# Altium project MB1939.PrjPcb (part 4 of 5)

## Sheet Power.SchDoc: Schematic sheet title to update
size A3; Date: Not used; ApprovedBy: Not used; CheckedBy: Not used; Author: Not used; CompanyName: STMicroelectronics; DrawnBy: Not used; Engineer: Not used; Organization: Not used; Address1: Not used; Address2: Not used; Address3: Not used; Address4: Not used; DocumentNumber: Not used; Revision: Not used; SheetNumber: 5; SheetTotal: 21
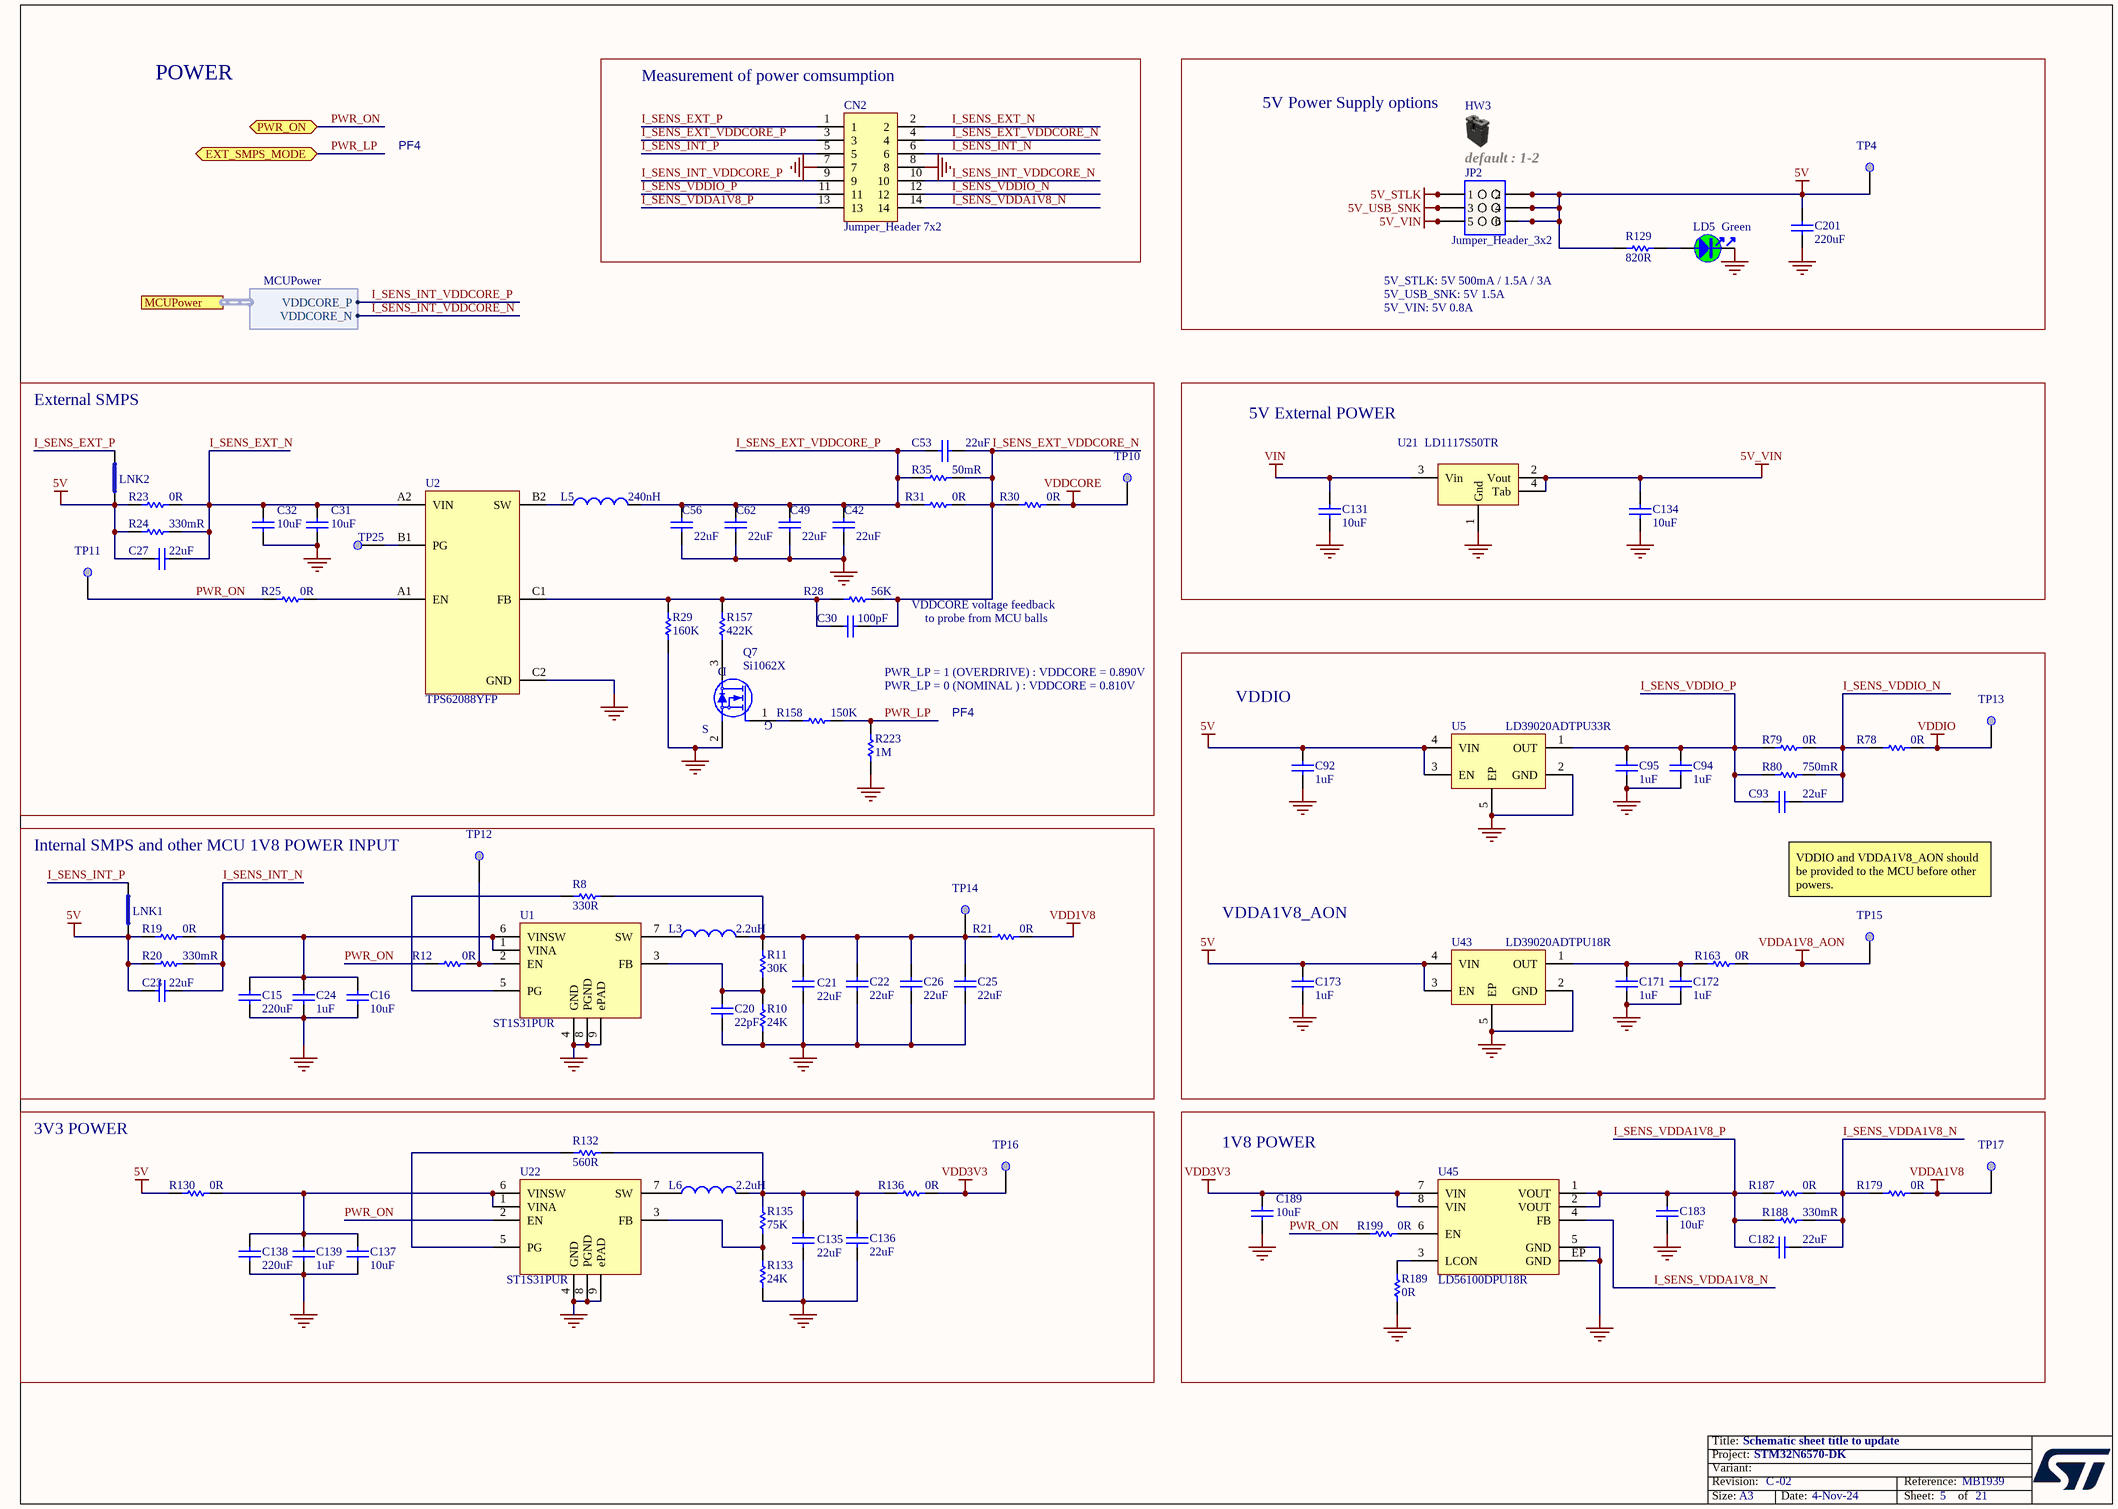
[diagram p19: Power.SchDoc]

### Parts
C15  value 220uF  [C1206_H1P6]  (hidden comment: Capacitor)
C16  value 10uF  [C0603]  (hidden comment: Capacitor)
C20  value 22pF  [C0402]  (hidden comment: Capacitor)
C21  value 22uF  [C0603]  (hidden comment: Capacitor)
C22  value 22uF  [C0603]  (hidden comment: Capacitor)
C23  value 22uF  [C0603]  (hidden comment: Capacitor)
C24  value 1uF  [C0402]  (hidden comment: Capacitor)
C25  value 22uF  [C0603]  (hidden comment: Capacitor)
C26  value 22uF  [C0603]  (hidden comment: Capacitor)
C27  value 22uF  [C0603]  (hidden comment: Capacitor)
C30  value 100pF  [C0402]  (hidden comment: Capacitor)
C31  value 10uF  [C0603]  (hidden comment: Capacitor)
C32  value 10uF  [C0603]  (hidden comment: Capacitor)
C42  value 22uF  [C0603]  (hidden comment: Capacitor)
C49  value 22uF  [C0603]  (hidden comment: Capacitor)
C53  value 22uF  [C0603]  (hidden comment: Capacitor)
C56  value 22uF  [C0603]  (hidden comment: Capacitor)
C62  value 22uF  [C0603]  (hidden comment: Capacitor)
C92  value 1uF  [C0402]  (hidden comment: Capacitor)
C93  value 22uF  [C0603]  (hidden comment: Capacitor)
C94  value 1uF  [C0402]  (hidden comment: Capacitor)
C95  value 1uF  [C0402]  (hidden comment: Capacitor)
C131  value 10uF  [C0805]  (hidden comment: Capacitor)
C134  value 10uF  [C0805]  (hidden comment: Capacitor)
C135  value 22uF  [C0603]  (hidden comment: Capacitor)
C136  value 22uF  [C0603]  (hidden comment: Capacitor)
C137  value 10uF  [C0603]  (hidden comment: Capacitor)
C138  value 220uF  [C1206_H1P6]  (hidden comment: Capacitor)
C139  value 1uF  [C0402]  (hidden comment: Capacitor)
C171  value 1uF  [C0402]  (hidden comment: Capacitor)
C172  value 1uF  [C0402]  (hidden comment: Capacitor)
C173  value 1uF  [C0402]  (hidden comment: Capacitor)
C182  value 22uF  [C0603]  (hidden comment: Capacitor)
C183  value 10uF  [C0603]  (hidden comment: Capacitor)
C189  value 10uF  [C0603]  (hidden comment: Capacitor)
C201  value 220uF  [C1206_H1P6]  (hidden comment: Capacitor)
CN2  value Jumper_Header 7x2  [CON_SAMTEC_TSW-107-07-X-D]  (hidden comment: Header 7x2)
HW3  Shunt Black 2.54mm  (value not drawn)  (mechanical)
JP2  value Jumper_Header_3x2  [CON_SAMTEC_TSM-103-01-X-DV]  (hidden comment: Jumper_Header 3x2)
L3  value 2.2uH  [IND_4025_WURTH_74404043022A]  (hidden comment: Inductor)
L5  value 240nH  [IND_MURATA_DFE201612P]  (hidden comment: Inductor)
L6  value 2.2uH  [IND_4025_WURTH_74404043022A]  (hidden comment: Inductor)
LD5  value Green  [LED_0603_OSRAM_LG-Q396-PS-35_GREEN_1A2K_H0P4]  (hidden comment: LED_green)
LNK1  link_200  [LINK200]  (value not drawn)  (no BOM)
LNK2  link_200  [LINK200]  (value not drawn)  (no BOM)
Q7  Manufacturer_Part_Number: Si1062X  [MOS_SC89-3L]  (hidden comment: MOSFET_N-CHANNEL)
R8  value 330R  [R0402]  (hidden comment: Resistor)
R10  value 24K  [R0402]  (hidden comment: Resistor)
R11  value 30K  [R0402]  (hidden comment: Resistor)
R12  value 0R  [R0402]  (hidden comment: Resistor)
R19  value 0R  [R0603]  (hidden comment: Resistor)
R20  value 330mR  [R0603]  (hidden comment: Resistor)
R21  value 0R  [R0603]  (hidden comment: Resistor)
R23  value 0R  [R0603]  (hidden comment: Resistor)
R24  value 330mR  [R0603]  (hidden comment: Resistor)
R25  value 0R  [R0402]  (hidden comment: Resistor)
R28  value 56K  [R0402]  (hidden comment: Resistor)
R29  value 160K  [R0402]  (hidden comment: Resistor)
R30  value 0R  [R0603]  (hidden comment: Resistor)
R31  value 0R  [R0603]  (hidden comment: Resistor)
R35  value 50mR  [R0603]  (hidden comment: Resistor)
R78  value 0R  [R0603]  (hidden comment: Resistor)
R79  value 0R  [R0603]  (hidden comment: Resistor)
R80  value 750mR  [R0603]  (hidden comment: Resistor)
R129  value 820R  [R0603]  (hidden comment: Resistor)
R130  value 0R  [R0603]  (hidden comment: Resistor)
R132  value 560R  [R0402]  (hidden comment: Resistor)
R133  value 24K  [R0402]  (hidden comment: Resistor)
R135  value 75K  [R0402]  (hidden comment: Resistor)
R136  value 0R  [R0603]  (hidden comment: Resistor)
R157  value 422K  [R0402]  (hidden comment: Resistor)
R158  value 150K  [R0402]  (hidden comment: Resistor)
R163  value 0R  [R0805]  (hidden comment: Resistor)
R179  value 0R  [R0603]  (hidden comment: Resistor)
R187  value 0R  [R0603]  (hidden comment: Resistor)
R188  value 330mR  [R0603]  (hidden comment: Resistor)
R189  value 0R  [R0402]  (hidden comment: Resistor)
R199  value 0R  [R0603]  (hidden comment: Resistor)
R223  value 1M  [R0402]  (hidden comment: Resistor)
TP4  Test Point  [TP_SMD_2MM]  (value not drawn)  (no BOM)
TP10  Test Point  [TP_SMD_2MM]  (value not drawn)  (no BOM)
TP11  Test Point  [TP_SMD_2MM]  (value not drawn)  (no BOM)
TP12  Test Point  [TP_SMD_2MM]  (value not drawn)  (no BOM)
TP13  Test Point  [TP_SMD_2MM]  (value not drawn)  (no BOM)
TP14  Test Point  [TP_SMD_2MM]  (value not drawn)  (no BOM)
TP15  Test Point  [TP_SMD_2MM]  (value not drawn)  (no BOM)
TP16  Test Point  [TP_SMD_2MM]  (value not drawn)  (no BOM)
TP17  Test Point  [TP_SMD_2MM]  (value not drawn)  (no BOM)
TP25  Test Point  [TP_SMD_1MM]  (value not drawn)  (no BOM)
U1  ST1S31PUR  [ICC_VFDFPN8-EPAD_3X3_P065]
U2  TPS62088YFP  [ICC_DSBGA6_YFP_0P80X1P20_H0P50_P040]
U5  value LD39020ADTPU33R  [REG_XDFN4-EPAD_CASE-711AJ_1X1_H0P4_P065]  (hidden comment: LD39020)
U21  LD1117S50TR  [REG_SOT223-TAB]
U22  ST1S31PUR  [ICC_VFDFPN8-EPAD_3X3_P065]
U43  value LD39020ADTPU18R  [REG_XDFN4-EPAD_CASE-711AJ_1X1_H0P4_P065]  (hidden comment: LD39020)
U45  LD56100DPU18R  [ICC_DFN8-EPAD_1P6X1P2_P040_H0P45]

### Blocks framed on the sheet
Measurement of power comsumption: CN2
5V Power Supply options: C201 HW3 JP2 LD5 R129 TP4
External SMPS: C27 C30-C32 C42 C49 C53 C56 C62 L5 LNK2 Q7 R23-R25 R28-R31 R35 R157 R158 R223 TP10 TP11 TP25 U2
5V External POWER: C131 C134 U21
Internal SMPS and other MCU 1V8 POWER INPUT: C15 C16 C20-C26 L3 LNK1 R8 R10-R12 R19-R21 TP12 TP14 U1
3V3 POWER: C135-C139 L6 R130 R132 R133 R135 R136 TP16 U22
1V8 POWER: C182 C183 C189 R179 R187-R189 R199 TP17 U45

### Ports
EXT_SMPS_MODE (bidir), MCUPower (harness MCUPower), PWR_ON (bidir)

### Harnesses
MCUPower: VDDCORE_P, VDDCORE_N

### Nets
5V: C23.2 C27.2 C92.2 C173.2 C201.2 JP2.2 JP2.4 JP2.6 LNK1.2 LNK2.2 R19.1 R20.1 R23.1 R24.1 R129.1 R130.1 TP4.1 U5.3(EN) U5.4(VIN) U43.3(EN) U43.4(VIN)
5V_STLK: JP2.1
5V_USB_SNK: JP2.3
5V_VIN: C134.2 JP2.5 U21.2(Vout) U21.4(Tab)
GND: C15.1 C16.1 C20.1 C21.1 C22.1 C24.1 C25.1 C26.1 C31.1 C32.1 C42.1 C49.1 C56.1 C62.1 C92.1 C94.1 C95.1 C131.1 C134.1 C135.1 C136.1 C137.1 C138.1 C139.1 C171.1 C172.1 C173.1 C183.1 C189.1 C201.1 CN2.7 CN2.8 LD5.2 Q7.2(S) R10.1 R29.1 R133.1 R189.1 R223.1 U1.4(GND) U1.8(PGND) U1.9(ePAD) U2.C2(GND) U5.2(GND) U5.5(EP) U21.1(Gnd) U22.4(GND) U22.8(PGND) U22.9(ePAD) U43.2(GND) U43.5(EP) U45.5(GND) U45.EP(GND)
VDD1V8: R21.2
VDD3V3: C189.2 R136.2 TP16.1 U45.7(VIN) U45.8(VIN)
VDDA1V8: R179.2 TP17.1
VDDA1V8_AON: R163.2 TP15.1
VDDCORE: R30.2 TP10.1
VDDIO: R78.2 TP13.1
VIN: C131.2 U21.3(Vin)
I_SENS_EXT_N: C27.1 C31.2 C32.2 CN2.2 R23.2 R24.2 U2.A2(VIN)
I_SENS_EXT_P: CN2.1 LNK2.1
I_SENS_EXT_VDDCORE_N: C30.2 C53.1 CN2.4 R28.2 R30.1 R31.2 R35.2
I_SENS_EXT_VDDCORE_P: C42.2 C49.2 C53.2 C56.2 C62.2 CN2.3 L5.2 R31.1 R35.1
I_SENS_INT_N: C15.2 C16.2 C23.1 C24.2 CN2.6 R19.2 R20.2 U1.1(VINA) U1.6(VINSW)
I_SENS_INT_P: CN2.5 LNK1.1
I_SENS_INT_VDDCORE_N: CN2.10 ; port MCUPower.VDDCORE_N
I_SENS_INT_VDDCORE_P: CN2.9 ; port MCUPower.VDDCORE_P
I_SENS_VDDA1V8_N: C182.1 CN2.14 R179.1 R187.2 R188.2 U45.4(FB)
I_SENS_VDDA1V8_P: C182.2 C183.2 CN2.13 R187.1 R188.1 U45.1(VOUT) U45.2(VOUT)
I_SENS_VDDIO_N: C93.1 CN2.12 R78.1 R79.2 R80.2
I_SENS_VDDIO_P: C93.2 C94.2 C95.2 CN2.11 R79.1 R80.1 U5.1(OUT)
PWR_LP: R158.1 R223.2 ; port EXT_SMPS_MODE  [project net PF4]
PWR_ON: R12.1 R25.1 R199.1 TP11.1 U22.2(EN) ; port PWR_ON
NetC20_2: C20.2 R10.2 R11.1 U1.3(FB)
NetC21_2: C21.2 C22.2 C25.2 C26.2 L3.2 R8.2 R11.2 R21.1 TP14.1
NetC30_1: C30.1 R28.1 R29.2 R157.2 U2.C1(FB)
NetC135_2: C135.2 C136.2 L6.2 R132.2 R135.2 R136.1
NetC137_2: C137.2 C138.2 C139.2 R130.2 U22.1(VINA) U22.6(VINSW)
NetC171_2: C171.2 C172.2 R163.1 U43.1(OUT)
NetL3_1: L3.1 U1.7(SW)
NetL5_1: L5.1 U2.B2(SW)
NetL6_1: L6.1 U22.7(SW)
NetLD5_1: LD5.1 R129.2
NetQ7_1: Q7.1(G) R158.2
NetQ7_3: Q7.3(D) R157.1
NetR8_1: R8.1 U1.5(PG)
NetR12_2: R12.2 TP12.1 U1.2(EN)
NetR25_2: R25.2 U2.A1(EN)
NetR132_1: R132.1 U22.5(PG)
NetR133_2: R133.2 R135.1 U22.3(FB)
NetR189_2: R189.2 U45.3(LCON)
NetR199_2: R199.2 U45.6(EN)
NetTP25_1: TP25.1 U2.B1(PG)

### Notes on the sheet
- POWER
- PF4
- default : 1-2
- 5V_STLK: 5V 500mA / 1.5A / 3A
- 5V_USB_SNK: 5V 1.5A
- 5V_VIN: 5V 0.8A
- VDDCORE voltage feedback
- to probe from MCU balls
- PWR_LP = 1 (OVERDRIVE) : VDDCORE = 0.890V
- PWR_LP = 0 (NOMINAL ) : VDDCORE = 0.810V
- VDDIO
- VDDA1V8_AON
- VDDIO and VDDA1V8_AON should be provided to the MCU before other powers.

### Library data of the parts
C15 C138 C201 = MCD-00104: Capacitor, MLCC, 220uF, 6V3, X5R, +/-20%, 1206, T=1.6mm; Part_Preference: Recommended; Manufacturer: MURATA; Manufacturer_Part_Number: GRM31CR60J227ME11; Order_Code_RS: 170-6396; Component_Country_Of_Origin: Japan°°; ShowFields: YES; ID: 2764
C16 C137 C183 = MCD-00099: Capacitor, MLCC, 10uF, 10V, X5R, +/-10%, 0603, T=0.8mm; Part_Preference: Recommended; Manufacturer: MURATA; Manufacturer_Part_Number: GRM188R61A106KE69D; Partial_Alternate_Internal_Part_Number: MCD-03152; Order_Code_RS: 2494233; Component_Country_Of_Origin: Japan°°; ShowFields: YES; ID: 2770
C20 = MCD-01783: Capacitor, MLCC, 22pF, 50V, NPO,+/-2%, 0402, T=0.5mm; Part_Preference: Recommended; Manufacturer: YAGEO; Manufacturer_Part_Number: CC0402GRNPO9BN220; Component_Country_Of_Origin: China; ShowFields: YES; ID: 3883
C21 C22 C25 C26 C135 C136 = MCD-00100: Capacitor, MLCC, 22uF, 6V3, X5R, +/-20%, 0603, T=0.8mm; Part_Preference: Recommended; Manufacturer: MURATA; Manufacturer_Part_Number: GRM188R60J226MEA0J; Component_Country_Of_Origin: Japan°°; ShowFields: YES; ID: 2766
C23 C27 C42 C49 C53 C56 C62 C93 C182 = MCD-00100: Capacitor, MLCC, 22uF, 6V3, X5R, +/-20%, 0603, T=0.8mm; Manufacturer_Part_Number: GRM188R60J226MEA0J; Manufacturer: MURATA; Part_Preference: Recommended; Component_Country_Of_Origin: Japan°°; ShowFields: YES; ID: 2766
C24 C92 C94 C95 C139 C171-C173 = MCD-00095: Capacitor, MLCC, 1uF, 25V, X5R, +/-10%, 0402, T=0.5mm; Part_Preference: Recommended; Manufacturer: MURATA; Manufacturer_Part_Number: GRM155R61E105KA12; Partial_Alternate_Internal_Part_Number: MCD-04188; Order_Code_RS: 2218855; Component_Country_Of_Origin: Japan°°; ShowFields: YES; ID: 2772
C30 = MCD-00205: Capacitor, MLCC, 100pF, 50V, NPO, +/-5%, 0402, T=0.5mm; Part_Preference: Recommended; Manufacturer: YAGEO; Manufacturer_Part_Number: CC0402JRNPO9BN101; Component_Country_Of_Origin: China; ShowFields: YES; ID: 2658
C31 C32 = MCD-00099: Capacitor, MLCC, 10uF, 10V, X5R, +/-10%, 0603, T=0.8mm; Manufacturer_Part_Number: GRM188R61A106KE69D; Manufacturer: MURATA; Part_Preference: Recommended; Partial_Alternate_Internal_Part_Number: MCD-03152; Order_Code_RS: 2494233; Component_Country_Of_Origin: Japan°°; ShowFields: YES; ID: 2770
C131 C134 = MCD-00014: Capacitor, MLCC, 10uF, 25V, X5R, +/-10%, 0805, T=0.85mm; Manufacturer_Part_Number: CC0805KRX5R8BB106; Manufacturer: YAGEO; Part_Preference: Recommended; Full_Alternate_Internal_Part_Number: MCD-02385; Partial_Alternate_Internal_Part_Number: MCD-03053; Component_Country_Of_Origin: China; ShowFields: YES; ID: 2468
C189 = MCD-00099: Capacitor, MLCC, 10uF, 10V, X5R, +/-10%, 0603, T=0.8mm; Manufacturer_Part_Number: GRM188R61A106KE69D; Manufacturer: MURATA; Part_Preference: Recommended; Partial_Alternate_Internal_Part_Number: MCD-03152; Order_Code_RS: 2494233; Component_Country_Of_Origin: Japan°°; ID: 2770; ShowFields: YES
CN2 = MCD-02123: Header, 7x2, 2.54mm, VR, TH, T=5.84mm/2.54mm; Part_Preference: Recommended; Part_Type: Connector; Manufacturer: SAMTEC; Manufacturer_Part_Number: TSW-107-07-G-D; Component_Country_Of_Origin: China, Costa Rica, Malaysia, USA, Vietnam; ShowFields: YES; ID: 4223
HW3 = MCD-00043: Jumper, 2.54mm, Black, 4.3A, 6.1mm, 5mR; Part_Type: Misc; Manufacturer: SAMTEC; Part_Preference: Recommended; Full_Alternate_Internal_Part_Number: MCD-02388; Manufacturer_HQ_COO: Unknown; Partial_Alternate_Internal_Part_Number: MCD-01849, MCD-01864; Value: SNT-100-BK-G; Component_Country_Of_Origin: China, Costa Rica, Malaysia, USA, Vietnam; ShowFields: YES; ID: 2551; Order_Code_RS: 158-7784; Alternate_EMS: A
JP2 = MCD-03177: Header, 3x2, 2.54mm, VR, SMD, T=9,65mm; Part_Type: Connector; Part_Preference: Recommended; Manufacturer: SAMTEC; Manufacturer_Part_Number: TSM-103-01-G-DV; ShowFields: YES; ID: 5293; Component_Country_Of_Origin: USA
L3 L6 = MCD-02242: Inductor, 2.2uH, +/-30%, 3,83A, 0R023, 4x4mm, T=2.5mm; Part_Preference: Recommended; Manufacturer: WURTH ELEKTRONIK; Manufacturer_Part_Number: 74404043022A; Component_Country_Of_Origin: Unknown; ShowFields: YES; ID: 4342
L5 = MCD-02477: Inductor, 240nH, +/-20%, 4.4A, 23mR, 0806, T=1.2mm; Part_Preference: Recommended; Manufacturer: MURATA; Manufacturer_Part_Number: DFE201612P-R24M=P2; Order_Code_RS: 167-0599; ShowFields: YES; ID: 4583; Component_Country_Of_Origin: China°
LD5 = MCD-00588: LED, Green, 2V, 20mA, 0603; Part_Preference: Recommended; Part_Type: Display; Manufacturer: OSRAM OPTO SEMICONDUCTORS; Manufacturer_Part_Number: LG Q396-PS-35; Partial_Alternate_Internal_Part_Number: MCD-02400, MCD-03155, MCD-02901; Component_Country_Of_Origin: Unknown; ShowFields: YES; ID: 3155
LNK1 LNK2 = MCD-02777: Track link on PCB 200um width for layout routing; Part_Type: Misc; Part_Preference: Recommended; ShowFields: YES; ID: 4889; Component_Country_Of_Origin: Unknown
Q7 = MCD-02221: Transistor, MOSFET, N-CH, 20V, 530mA, SC89-3; Part_Preference: Recommended; Manufacturer: VISHAY; Order_Code_RS: 812-3044; Component_Country_Of_Origin: Philippines; Value: Si1062X; ShowFields: YES; ID: 4321
R8 = MCD-00062: Resistor, 330R, 0402, +/-1%, 1/16W; Part_Preference: Recommended; Manufacturer: YAGEO; Manufacturer_Part_Number: RC0402FR-07330RL; Order_Code_RS: 9239170; Component_Country_Of_Origin: China; ShowFields: YES; ID: 2529
R10 R133 = MCD-00435: Resistor, 24K, 0402, +/-1%, 1/16W; Part_Preference: Recommended; Manufacturer: YAGEO; Manufacturer_Part_Number: RC0402FR-0724KL; Component_Country_Of_Origin: China; ShowFields: YES; ID: 2845
R11 = MCD-02979: Resistor, 30K, 0402, +/-0.1%, 1/16W, +/-25ppm/°C; Part_Preference: Recommended; Manufacturer: YAGEO; Manufacturer_Part_Number: RT0402BRD0730KL; Order_Code_RS: 199-1325; ShowFields: YES; ID: 5095; Component_Country_Of_Origin: Taiwan
R12 R25 = MCD-00052: Resistor, 0R, 0402, +/-5%, 1/16W; Manufacturer_Part_Number: RC0402JR-070RL; Manufacturer: YAGEO; Part_Preference: Recommended; Order_Code_RS: 9232516RL; Component_Country_Of_Origin: China; ShowFields: YES; ID: 2540
R19 R23 R130 = MCD-00056: Resistor, 0R, 0603, +/-5%, 1/10W; Manufacturer_Part_Number: RC0603JR-070RL; Manufacturer: YAGEO; Part_Preference: Recommended; Order_Code_RS: 9233130RL; Component_Country_Of_Origin: China; ShowFields: YES; ID: 2536
R20 R24 R188 = MCD-03197: Resistor, 330mR, 0603, +/-1%, 1/5W; Part_Preference: Recommended; Manufacturer: YAGEO; Manufacturer_Part_Number: PT0603FR-7W0R33L; Full_Alternate_Internal_Part_Number: MCD-04231; ShowFields: YES; ID: 5313; Component_Country_Of_Origin: Taiwan
R21 R30 R31 R136 = MCD-00181: Resistor, 0R, 0603, +/- 0.5mR, 1/4W; Manufacturer_Part_Number: PMR03EZPJ000; Manufacturer: ROHM SEMICONDUCTOR; Part_Preference: Recommended; Component_Country_Of_Origin: Philippines, Thailand°°; ShowFields: YES; ID: 2691
R28 = MCD-00493: Resistor, 56K, 0402, +/-1%, 1/16W; Part_Preference: Recommended; Manufacturer: YAGEO; Manufacturer_Part_Number: RC0402FR-0756KL; Component_Country_Of_Origin: China; ShowFields: YES; ID: 2784
R29 = MCD-00405: Resistor, 160K, 0402, +/-1%, 1/16W; Part_Preference: Recommended; Manufacturer: YAGEO; Manufacturer_Part_Number: RC0402FR-07160KL; Component_Country_Of_Origin: China; ShowFields: YES; ID: 2873
R35 = MCD-02233: Resistor, 50mR, 0603, +/-1%, 1/3W; Part_Preference: Recommended; Manufacturer: PANASONIC; Manufacturer_Part_Number: ERJ-3BWFR050V; Order_Code_RS: RA; Component_Country_Of_Origin: Japan; ShowFields: YES; ID: 4333
R78 R79 R179 R187 = MCD-00181: Resistor, 0R, 0603, +/- 0.5mR, 1/4W; Part_Preference: Recommended; Manufacturer: ROHM SEMICONDUCTOR; Manufacturer_Part_Number: PMR03EZPJ000; Component_Country_Of_Origin: Philippines, Thailand°°; ShowFields: YES; ID: 2691
R80 = MCD-03198: Resistor, 750mR, 0603, +/-1%, 1/5W; Part_Preference: Recommended; Manufacturer: YAGEO; Manufacturer_Part_Number: PT0603FR-7W0R75L; ShowFields: YES; ID: 5314; Component_Country_Of_Origin: Taiwan
R129 = MCD-00528: Resistor, 820R, 0603, +/-1%, 1/10W; Manufacturer_Part_Number: RC0603FR-07820RL; Manufacturer: YAGEO; BMS_Part_Number: 9129759; Part_Preference: Recommended; Component_Country_Of_Origin: China; ShowFields: YES; ID: 3218
R132 = MCD-00489: Resistor, 560R, 0402, +/-1%, 1/16W; Part_Preference: Recommended; Manufacturer: YAGEO; Manufacturer_Part_Number: RC0402FR-07560RL; Component_Country_Of_Origin: China; ShowFields: YES; ID: 2789
R135 = MCD-00521: Resistor, 75K, 0402, +/-1%, 1/16W; Part_Preference: Recommended; Manufacturer: YAGEO; Manufacturer_Part_Number: RC0402FR-0775KL; Component_Country_Of_Origin: China; ShowFields: YES; ID: 3220
R157 = MCD-04136: Resistor, 422K, 0402, +/-1%, 1/16W; Part_Preference: Recommended; Manufacturer: YAGEO; Manufacturer_Part_Number: RC0402FR-07422KL; ShowFields: YES; ID: 6252; Component_Country_Of_Origin: China
R158 = MCD-00165: Resistor, 150K, 0402, +/-1%, 1/16W; Manufacturer_Part_Number: RC0402FR-07150KL; Manufacturer: YAGEO; BMS_Part_Number: 9131032; Part_Preference: Recommended; Component_Country_Of_Origin: China; ShowFields: YES; ID: 2702
R163 = MCD-00179: Resistor, 0R, 0805, +/-5%, 1/8W; Part_Preference: Recommended; Manufacturer: YAGEO; Manufacturer_Part_Number: RC0805JR-070RL; Component_Country_Of_Origin: China; ShowFields: YES; ID: 2685
R189 = MCD-00052: Resistor, 0R, 0402, +/-5%, 1/16W; Manufacturer_Part_Number: RC0402JR-070RL; Manufacturer: YAGEO; Part_Preference: Recommended; Order_Code_RS: 9232516RL; Component_Country_Of_Origin: China; ID: 2540; ShowFields: YES
R199 = MCD-00056: Resistor, 0R, 0603, +/-5%, 1/10W; Manufacturer_Part_Number: RC0603JR-070RL; Manufacturer: YAGEO; Part_Preference: Recommended; Order_Code_RS: 9233130RL; Component_Country_Of_Origin: China; ID: 2536; ShowFields: YES
R223 = MCD-00182: Resistor, 1M, 0402, +/-1%, 1/16W; Manufacturer_Part_Number: RC0402FR-071ML; Manufacturer: YAGEO; BMS_Part_Number: 9131778; Part_Preference: Recommended; Order_Code_RS: 618-6194; Component_Country_Of_Origin: China; ShowFields: YES; ID: 2686
TP4 TP10-TP17 = MCD-00177: Test Point, SMD, 2mm; Part_Type: Misc; Part_Preference: Recommended; ShowFields: YES; ID: 2690; Component_Country_Of_Origin: Unknown
TP25 = MCD-00074: Test Point, SMD, 1mm; Part_Type: Misc; Part_Preference: Recommended; Component_Country_Of_Origin: Unknown; ShowFields: YES; ID: 2518
U1 U22 = MCD-02243: Regulator, 3A, DC step-down switching; Part_Preference: Recommended; Part_Type: IC; Manufacturer: STMICROELECTRONICS; Manufacturer_HQ_COO: EU; Component_Country_Of_Origin: Malaysia; ShowFields: YES; ID: 4343; Order_Code_RS: 168-7852
U2 = MCD-02469: IC, 2V4 to 5V5 Input, Tiny 6-pin, 3A, Step-Down converter in 1.2x0.8mm wafer chip scale package and suitable for embedding; Part_Preference: Recommended; Manufacturer: TEXAS INSTRUMENTS; Component_Country_Of_Origin: Philippines; ShowFields: YES; ID: 4575
U5 = MCD-02222: LDO, 200mA, Very low quiescent current linear regulator IC; Part_Preference: Recommended; Manufacturer: STMICROELECTRONICS; Manufacturer_HQ_COO: EU; Component_Country_Of_Origin: China; ShowFields: YES; ID: 4322
U21 = MCD-00088: LDO, Adjustable and fixed low drop positive voltage regulator; Part_Type: IC; Manufacturer: STMICROELECTRONICS; BMS_Part_Number: 9176133; Part_Preference: Recommended; Manufacturer_HQ_COO: EU; Component_Country_Of_Origin: China; ShowFields: YES; ID: 2503; Order_Code_RS: 165-7748
U43 = MCD-02224: LDO, 200mA, Very low quiescent current linear regulator IC; Part_Preference: Recommended; Manufacturer: STMICROELECTRONICS; Manufacturer_HQ_COO: EU; Component_Country_Of_Origin: China; ShowFields: YES; ID: 4324
U45 = MCD-02937: LDO, 1A, 1V8, Fast transient, ultra-low noise; Part_Type: IC; Part_Preference: Recommended; Manufacturer: STMICROELECTRONICS; Order_Code_RS: 203-3404; Component_Country_Of_Origin: China; ShowFields: YES; ID: 5053

## Sheet STM32_microcontroller_IOs.SchDoc: STM32_microcontroller_IOs
size A3; Date: Not used; ApprovedBy: Not used; CheckedBy: Not used; Author: Not used; CompanyName: STMicroelectronics; DrawnBy: Not used; Engineer: Not used; Organization: Not used; Address1: Not used; Address2: Not used; Address3: Not used; Address4: Not used; DocumentNumber: Not used; Revision: Not used; SheetNumber: 3; SheetTotal: 21
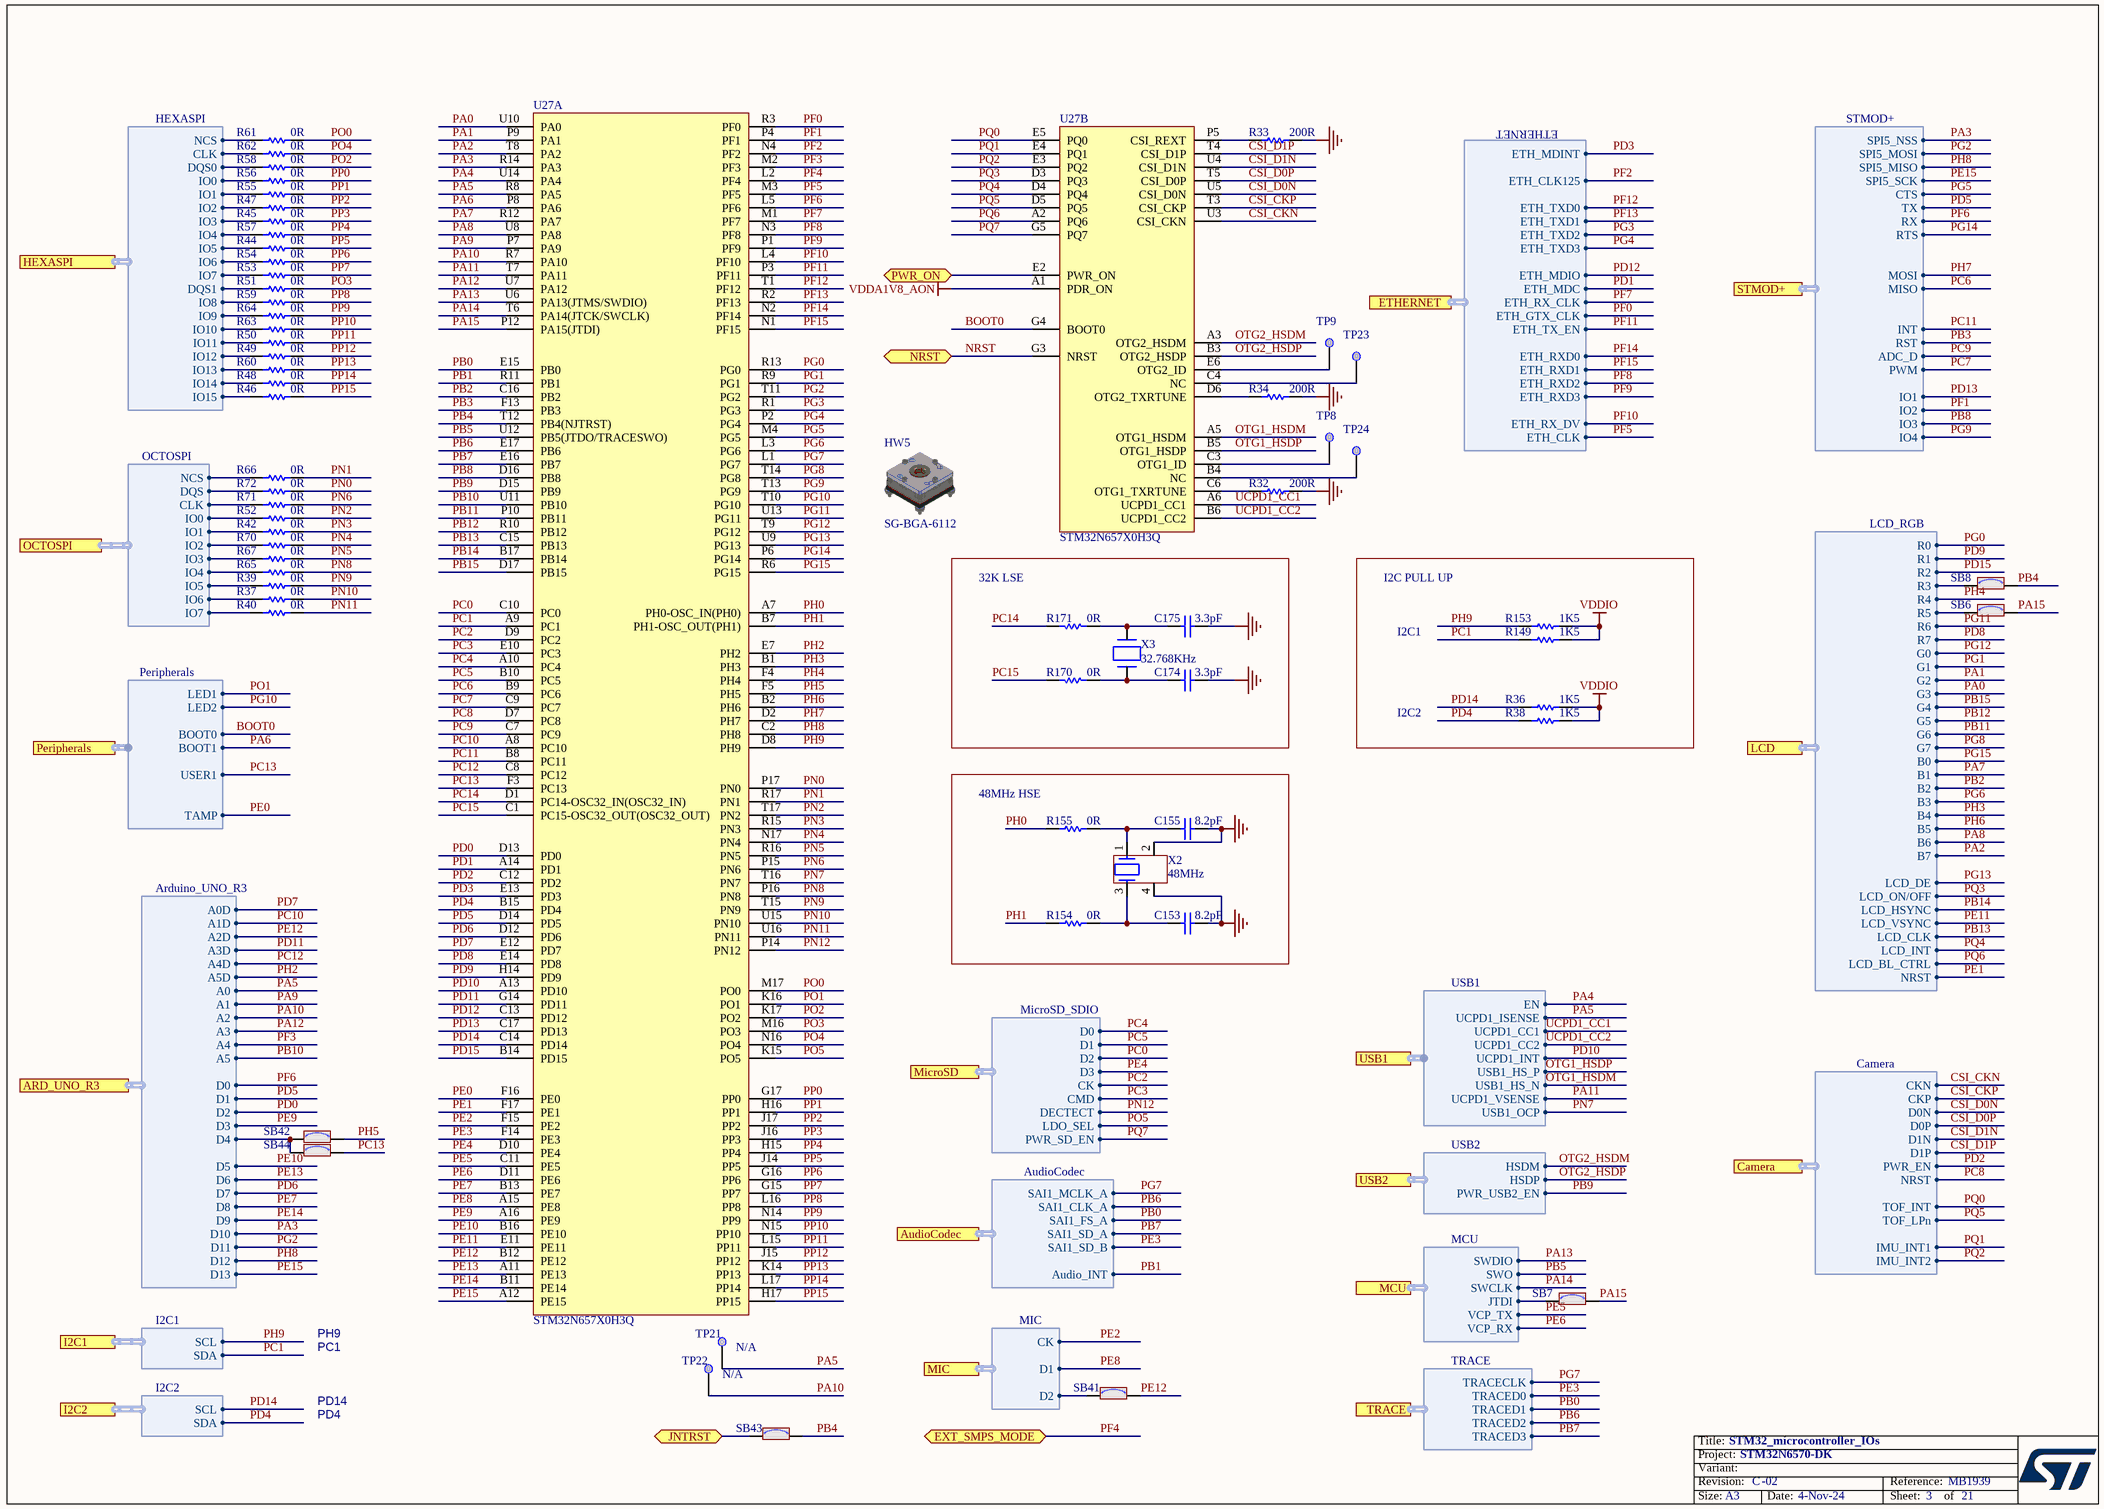
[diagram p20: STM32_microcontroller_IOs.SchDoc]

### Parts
C153  value 8.2pF  [C0402]  (hidden comment: Capacitor)
C155  value 8.2pF  [C0402]  (hidden comment: Capacitor)
C174  value 3.3pF  [C0402]  (hidden comment: Capacitor)
C175  value 3.3pF  [C0402]  (hidden comment: Capacitor)
HW5  value SG-BGA-6112  (hidden comment: SOCKET_BGA289)  (mechanical)
R32  value 200R  [R0402]  (hidden comment: Resistor)
R33  value 200R  [R0402]  (hidden comment: Resistor)
R34  value 200R  [R0402]  (hidden comment: Resistor)
R36  value 1K5  [R0402]  (hidden comment: Resistor)
R37  value 0R  [R0402]  (hidden comment: Resistor)
R38  value 1K5  [R0402]  (hidden comment: Resistor)
R39  value 0R  [R0402]  (hidden comment: Resistor)
R40  value 0R  [R0402]  (hidden comment: Resistor)
R42  value 0R  [R0402]  (hidden comment: Resistor)
R44  value 0R  [R0402]  (hidden comment: Resistor)
R45  value 0R  [R0402]  (hidden comment: Resistor)
R46  value 0R  [R0402]  (hidden comment: Resistor)
R47  value 0R  [R0402]  (hidden comment: Resistor)
R48  value 0R  [R0402]  (hidden comment: Resistor)
R49  value 0R  [R0402]  (hidden comment: Resistor)
R50  value 0R  [R0402]  (hidden comment: Resistor)
R51  value 0R  [R0402]  (hidden comment: Resistor)
R52  value 0R  [R0402]  (hidden comment: Resistor)
R53  value 0R  [R0402]  (hidden comment: Resistor)
R54  value 0R  [R0402]  (hidden comment: Resistor)
R55  value 0R  [R0402]  (hidden comment: Resistor)
R56  value 0R  [R0402]  (hidden comment: Resistor)
R57  value 0R  [R0402]  (hidden comment: Resistor)
R58  value 0R  [R0402]  (hidden comment: Resistor)
R59  value 0R  [R0402]  (hidden comment: Resistor)
R60  value 0R  [R0402]  (hidden comment: Resistor)
R61  value 0R  [R0402]  (hidden comment: Resistor)
R62  value 0R  [R0402]  (hidden comment: Resistor)
R63  value 0R  [R0402]  (hidden comment: Resistor)
R64  value 0R  [R0402]  (hidden comment: Resistor)
R65  value 0R  [R0402]  (hidden comment: Resistor)
R66  value 0R  [R0402]  (hidden comment: Resistor)
R67  value 0R  [R0402]  (hidden comment: Resistor)
R70  value 0R  [R0402]  (hidden comment: Resistor)
R71  value 0R  [R0402]  (hidden comment: Resistor)
R72  value 0R  [R0402]  (hidden comment: Resistor)
R149  value 1K5  [R0402]  (hidden comment: Resistor)
R153  value 1K5  [R0402]  (hidden comment: Resistor)
R154  value 0R  [R0402]  (hidden comment: Resistor)
R155  value 0R  [R0402]  (hidden comment: Resistor)
R170  value 0R  [R0402]  (hidden comment: Resistor)
R171  value 0R  [R0402]  (hidden comment: Resistor)
SB6  SB_ON  [SOLDER-BRIDGE_R0402-0R]  (value not drawn)
SB7  SB_ON  [SOLDER-BRIDGE_R0402-0R]  (value not drawn)
SB8  SB_ON  [SOLDER-BRIDGE_R0402-0R]  (value not drawn)
SB41  SB_ON  [SOLDER-BRIDGE_R0603-0R]  (value not drawn)
SB42  SB_ON  [SOLDER-BRIDGE_R0402-0R]  (value not drawn)
SB43  SB_ON  [SOLDER-BRIDGE_R0402-0R]  (value not drawn)
SB44  SB_ON  [SOLDER-BRIDGE_R0402-0R]  (value not drawn)
TP8  Test Point  [TP_SMD_1MM]  (value not drawn)  (no BOM)
TP9  Test Point  [TP_SMD_1MM]  (value not drawn)  (no BOM)
TP21  Test Point  [TP_SMD_2MM]  (value not drawn)  (no BOM)
TP22  Test Point  [TP_SMD_2MM]  (value not drawn)  (no BOM)
TP23  Test Point  [TP_SMD_1MM]  (value not drawn)  (no BOM)
TP24  Test Point  [TP_SMD_1MM]  (value not drawn)  (no BOM)
U27  STM32N657X0H3Q  [ICC_VFBGA264_14X14_P080_SOCKET_IRONWOOD_SG-BGA-6112MF]  (parts A,B of 3)
X2  value 48MHz  [CRY_NX1612SA_4P]  (hidden comment: XTAL_4_PINS)
X3  value 32.768KHz  [CRY_NX2012SA_2P]  (hidden comment: XTAL_2_PINS)

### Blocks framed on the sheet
32K LSE: C174 C175 R170 R171 X3
48MHz HSE: C153 C155 R154 R155 X2

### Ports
ARD_UNO_R3 (harness Arduino_UNO_R3), AudioCodec (harness AudioCodec), Camera (harness Camera), ETHERNET (harness ETHERNET), EXT_SMPS_MODE (bidir), HEXASPI (harness HEXASPI), I2C1 (harness I2C1), I2C2 (harness I2C2), JNTRST (bidir), LCD (harness LCD_RGB), MCU (harness MCU), MIC (harness MIC), MicroSD (harness MicroSD_SDIO), NRST (bidir), OCTOSPI (harness OCTOSPI), Peripherals (harness Peripherals), PWR_ON (bidir), STMOD+ (harness STMOD+), TRACE (harness TRACE), USB1 (harness USB1), USB2 (harness USB2)

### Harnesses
Arduino_UNO_R3: A0, A1, A2, A3, A4, A5, D0, D1, D2, D3, D4, D5, D6, D7, D8, D9, D10, D11, D12, D13, A0D, A1D, A2D, A3D, A4D, A5D
AudioCodec: SAI1_MCLK_A, SAI1_CLK_A, SAI1_FS_A, SAI1_SD_A, SAI1_SD_B, Audio_INT
Camera: CKN, CKP, D0N, D0P, D1N, D1P, PWR_EN, NRST, TOF_INT, TOF_LPn, IMU_INT1, IMU_INT2
ETHERNET: ETH_MDINT, ETH_CLK125, ETH_TXD0, ETH_MDIO, ETH_MDC, ETH_RX_CLK, ETH_GTX_CLK, ETH_TX_EN, ETH_RXD0, ETH_RX_DV, ETH_CLK, ETH_TXD1, ETH_TXD2, ETH_TXD3, ETH_RXD1, ETH_RXD2, ETH_RXD3
HEXASPI: IO1, IO0, DQS0, NCS, IO2, IO3, IO5, IO4, IO6, IO7, CLK, DQS1, IO8, IO9, IO10, IO11, IO12, IO13, IO14, IO15
LCD_RGB: R0, R1, G0, B0, R2, R3, R4, R5, R6, R7, G1, G2, G3, G4, G5, G6, G7, B1, B2, B3, B4, B5, B6, B7, LCD_DE, LCD_ON/OFF, LCD_HSYNC, LCD_VSYNC, LCD_CLK, LCD_INT, LCD_BL_CTRL, NRST
OCTOSPI: IO1, IO0, CLK, NCS, IO2, IO3, IO5, IO4, IO6, IO7, DQS
MicroSD_SDIO: D0, D1, D2, D3, CK, CMD, DECTECT, LDO_SEL, PWR_SD_EN
STMOD+: CTS, TX, RX, RTS, MOSI, MISO, INT, RST, ADC_D, PWM, IO1, IO2, IO3, IO4, SPI5_SCK, SPI5_MISO, SPI5_MOSI, SPI5_NSS
USB1: UCPD1_CC1, UCPD1_CC2, UCPD1_ISENSE, USB1_HS_P, USB1_HS_N, UCPD1_VSENSE, UCPD1_INT, USB1_OCP, EN
USB2: HSDM, PWR_USB2_EN, HSDP
TRACE: TRACECLK, TRACED2, TRACED0, TRACED3, TRACED1
MCU: SWDIO, SWO, VCP_TX, SWCLK, VCP_RX, JTDI
I2C2: SCL, SDA
I2C1: SCL, SDA
Peripherals: LED1, LED2, BOOT0, BOOT1, USER1, TAMP
MIC: CK, D1, D2

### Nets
GND: C153.1 C155.1 C174.1 C175.1 R32.2 R33.2 R34.2 X2.2 X2.4
VDDA1V8_AON: U27.A1(PDR_ON)
VDDIO: R36.1 R38.1 R149.1 R153.1
ARD_D4: SB42.1 SB44.1 ; port ARD_UNO_R3.D4
BOOT0: U27.G4(BOOT0) ; port Peripherals.BOOT0
CSI_CKN: U27.U3(CSI_CKN) ; port Camera.CKN
CSI_CKP: U27.T3(CSI_CKP) ; port Camera.CKP
CSI_D0N: U27.U5(CSI_D0N) ; port Camera.D0N  [project net CSI_D0_N]
CSI_D0P: U27.T5(CSI_D0P) ; port Camera.D0P  [project net CSI_D0_P]
CSI_D1N: U27.U4(CSI_D1N) ; port Camera.D1N  [project net CSI_D1_N]
CSI_D1P: U27.T4(CSI_D1P) ; port Camera.D1P  [project net CSI_D1_P]
D2: SB41.1 ; port MIC.D2
HEXASPI_CLK: R62.1 ; port HEXASPI.CLK
HEXASPI_DQS0: R58.1 ; port HEXASPI.DQS0
HEXASPI_DQS1: R51.1 ; port HEXASPI.DQS1
HEXASPI_IO0: R56.1 ; port HEXASPI.IO0
HEXASPI_IO1: R55.1 ; port HEXASPI.IO1
HEXASPI_IO2: R47.1 ; port HEXASPI.IO2
HEXASPI_IO3: R45.1 ; port HEXASPI.IO3
HEXASPI_IO4: R57.1 ; port HEXASPI.IO4
HEXASPI_IO5: R44.1 ; port HEXASPI.IO5
HEXASPI_IO6: R54.1 ; port HEXASPI.IO6
HEXASPI_IO7: R53.1 ; port HEXASPI.IO7
HEXASPI_IO8: R59.1 ; port HEXASPI.IO8
HEXASPI_IO9: R64.1 ; port HEXASPI.IO9
HEXASPI_IO10: R63.1 ; port HEXASPI.IO10
HEXASPI_IO11: R50.1 ; port HEXASPI.IO11
HEXASPI_IO12: R49.1 ; port HEXASPI.IO12
HEXASPI_IO13: R60.1 ; port HEXASPI.IO13
HEXASPI_IO14: R48.1 ; port HEXASPI.IO14
HEXASPI_IO15: R46.1 ; port HEXASPI.IO15
HEXASPI_NCS: R61.1 ; port HEXASPI.NCS
JNTRST: SB43.1 ; port JNTRST
LCD_R3: SB8.1 ; port LCD.R3
LCD_R5: SB6.1 ; port LCD.R5
MCU.JTDI: SB7.1 ; port MCU.JTDI
NRST: U27.G3(NRST) ; port NRST
OCTOSPI_CLK: R71.1 ; port OCTOSPI.CLK
OCTOSPI_DQS: R72.1 ; port OCTOSPI.DQS
OCTOSPI_IO0: R52.1 ; port OCTOSPI.IO0
OCTOSPI_IO1: R42.1 ; port OCTOSPI.IO1
OCTOSPI_IO2: R70.1 ; port OCTOSPI.IO2
OCTOSPI_IO3: R67.1 ; port OCTOSPI.IO3
OCTOSPI_IO4: R65.1 ; port OCTOSPI.IO4
OCTOSPI_IO5: R39.1 ; port OCTOSPI.IO5
OCTOSPI_IO6: R37.1 ; port OCTOSPI.IO6
OCTOSPI_IO7: R40.1 ; port OCTOSPI.IO7
OCTOSPI_NCS: R66.1 ; port OCTOSPI.NCS
OTG1_HSDM: U27.A5(OTG1_HSDM) ; port USB1.USB1_HS_N  [project net OTG1_HS_N]
OTG1_HSDP: U27.B5(OTG1_HSDP) ; port USB1.USB1_HS_P  [project net OTG1_HS_P]
OTG2_HSDM: U27.A3(OTG2_HSDM) ; port USB2.HSDM  [project net OTG2_HSD_N]
OTG2_HSDP: U27.B3(OTG2_HSDP) ; port USB2.HSDP  [project net OTG2_HSD_P]
PA0: U27.U10(PA0) ; port LCD.G3  [project net LCD_G3]
PA1: U27.P9(PA1) ; port LCD.G2  [project net LCD_G2]
PA2: U27.T8(PA2) ; port LCD.B7  [project net LCD_B7]
PA3: U27.R14(PA3) ; port ARD_UNO_R3.D10, port STMOD+.SPI5_NSS  [project net ARD_D10]
PA4: U27.U14(PA4) ; port USB1.EN
PA5: TP21.1 U27.R8(PA5) ; port ARD_UNO_R3.A0, port USB1.UCPD1_ISENSE  [project net ARD_A0]
PA6: U27.P8(PA6) ; port Peripherals.BOOT1  [project net BOOT1]
PA7: U27.R12(PA7) ; port LCD.B1  [project net LCD_B1]
PA8: U27.U8(PA8) ; port LCD.B6  [project net LCD_B6]
PA9: U27.P7(PA9) ; port ARD_UNO_R3.A1  [project net ARD_A1]
PA10: TP22.1 U27.R7(PA10) ; port ARD_UNO_R3.A2  [project net ARD_A2]
PA11: U27.T7(PA11) ; port USB1.UCPD1_VSENSE
PA12: U27.U7(PA12) ; port ARD_UNO_R3.A3  [project net ARD_A3]
PA13: U27.U6(PA13(JTMS/SWDIO)) ; port MCU.SWDIO  [project net MCU.SWDIO]
PA14: U27.T6(PA14(JTCK/SWCLK)) ; port MCU.SWCLK  [project net MCU.SWCLK]
PA15: SB6.2 SB7.2 U27.P12(PA15(JTDI))
PB0: U27.E15(PB0) ; port AudioCodec.SAI1_FS_A, port TRACE.TRACED1
PB1: U27.R11(PB1) ; port AudioCodec.Audio_INT  [project net AUDIO_INT]
PB2: U27.C16(PB2) ; port LCD.B2  [project net LCD_B2]
PB3: U27.F13(PB3) ; port STMOD+.RST
PB4: SB8.2 SB43.2 U27.T12(PB4(NJTRST))
PB5: U27.U12(PB5(JTDO/TRACESWO)) ; port MCU.SWO  [project net MCU.SWO]
PB6: U27.E17(PB6) ; port AudioCodec.SAI1_CLK_A, port TRACE.TRACED2
PB7: U27.E16(PB7) ; port AudioCodec.SAI1_SD_A, port TRACE.TRACED3
PB8: U27.D16(PB8) ; port STMOD+.IO3
PB9: U27.D15(PB9) ; port USB2.PWR_USB2_EN
PB10: U27.U11(PB10) ; port ARD_UNO_R3.A5  [project net ARD_A5]
PB11: U27.P10(PB11) ; port LCD.G6  [project net LCD_G6]
PB12: U27.R10(PB12) ; port LCD.G5  [project net LCD_G5]
PB13: U27.C15(PB13) ; port LCD.LCD_CLK  [project net LCD_CLK]
PB14: U27.B17(PB14) ; port LCD.LCD_HSYNC  [project net LCD_HSYNC]
PB15: U27.D17(PB15) ; port LCD.G4  [project net LCD_G4]
PC0: U27.C10(PC0) ; port MicroSD.D2
PC1: R149.2 U27.A9(PC1) ; port I2C1.SDA  [project net ARD_D14]
PC2: U27.D9(PC2) ; port MicroSD.CK
PC3: U27.E10(PC3) ; port MicroSD.CMD
PC4: U27.A10(PC4) ; port MicroSD.D0
PC5: U27.B10(PC5) ; port MicroSD.D1
PC6: U27.B9(PC6) ; port STMOD+.MISO
PC7: U27.C9(PC7) ; port STMOD+.PWM
PC8: U27.D7(PC8) ; port Camera.NRST  [project net NRST_CAM]
PC9: U27.C7(PC9) ; port STMOD+.ADC_D
PC10: U27.A8(PC10) ; port ARD_UNO_R3.A1D  [project net ARD_A1D]
PC11: U27.B8(PC11) ; port STMOD+.INT
PC12: U27.C8(PC12) ; port ARD_UNO_R3.A4D  [project net ARD_A4D]
PC13: SB44.2 U27.F3(PC13) ; port Peripherals.USER1
PC14: R171.2 U27.D1(PC14-OSC32_IN(OSC32_IN))
PC15: R170.2 U27.C1(PC15-OSC32_OUT(OSC32_OUT))
PD0: U27.D13(PD0) ; port ARD_UNO_R3.D2  [project net ARD_D2]
PD1: U27.A14(PD1) ; port ETHERNET.ETH_MDC  [project net ETH_MDC]
PD2: U27.C12(PD2) ; port Camera.PWR_EN  [project net EN_MODULE]
PD3: U27.E13(PD3) ; port ETHERNET.ETH_MDINT  [project net ETH_MDINT]
PD4: R38.2 U27.B15(PD4) ; port I2C2.SDA  [project net I2C2_SDA]
PD5: U27.D14(PD5) ; port ARD_UNO_R3.D1, port STMOD+.TX  [project net ARD_D1]
PD6: U27.D12(PD6) ; port ARD_UNO_R3.D7  [project net ARD_D7]
PD7: U27.E12(PD7) ; port ARD_UNO_R3.A0D  [project net ARD_A0D]
PD8: U27.E14(PD8) ; port LCD.R7  [project net LCD_R7]
PD9: U27.H14(PD9) ; port LCD.R1  [project net LCD_R1]
PD10: U27.A13(PD10) ; port USB1.UCPD1_INT
PD11: U27.G14(PD11) ; port ARD_UNO_R3.A3D  [project net ARD_A3D]
PD12: U27.C13(PD12) ; port ETHERNET.ETH_MDIO  [project net ETH_MDIO]
PD13: U27.C17(PD13) ; port STMOD+.IO1
PD14: R36.2 U27.C14(PD14) ; port I2C2.SCL  [project net I2C2_SCL]
PD15: U27.B14(PD15) ; port LCD.R2  [project net LCD_R2]
PE0: U27.F16(PE0) ; port Peripherals.TAMP
PE1: U27.F17(PE1) ; port LCD.NRST  [project net LCD_NRST]
PE2: U27.F15(PE2) ; port MIC.CK  [project net CK]
PE3: U27.F14(PE3) ; port AudioCodec.SAI1_SD_B, port TRACE.TRACED0
PE4: U27.D10(PE4) ; port MicroSD.D3
PE5: U27.C11(PE5) ; port MCU.VCP_TX  [project net MCU.VCP_TX]
PE6: U27.D11(PE6) ; port MCU.VCP_RX  [project net MCU.VCP_RX]
PE7: U27.B13(PE7) ; port ARD_UNO_R3.D8  [project net ARD_D8]
PE8: U27.A15(PE8) ; port MIC.D1  [project net D1]
PE9: U27.A16(PE9) ; port ARD_UNO_R3.D3  [project net ARD_D3]
PE10: U27.B16(PE10) ; port ARD_UNO_R3.D5  [project net ARD_D5]
PE11: U27.E11(PE11) ; port LCD.LCD_VSYNC  [project net LCD_VSYNC]
PE12: SB41.2 U27.B12(PE12) ; port ARD_UNO_R3.A2D  [project net ARD_A2D]
PE13: U27.A11(PE13) ; port ARD_UNO_R3.D6  [project net ARD_D6]
PE14: U27.B11(PE14) ; port ARD_UNO_R3.D9  [project net ARD_D9]
PE15: U27.A12(PE15) ; port ARD_UNO_R3.D13, port STMOD+.SPI5_SCK  [project net ARD_D13]
PF0: U27.R3(PF0) ; port ETHERNET.ETH_GTX_CLK  [project net ETH_GTX_CLK]
PF1: U27.P4(PF1) ; port STMOD+.IO2
PF2: U27.N4(PF2) ; port ETHERNET.ETH_CLK125  [project net ETH_CLK125]
PF3: U27.M2(PF3) ; port ARD_UNO_R3.A4  [project net ARD_A4]
PF4: U27.L2(PF4) ; port EXT_SMPS_MODE
PF5: U27.M3(PF5) ; port ETHERNET.ETH_CLK  [project net ETH_CLK]
PF6: U27.L5(PF6) ; port ARD_UNO_R3.D0, port STMOD+.RX  [project net ARD_D0]
PF7: U27.M1(PF7) ; port ETHERNET.ETH_RX_CLK  [project net ETH_RX_CLK]
PF8: U27.N3(PF8) ; port ETHERNET.ETH_RXD2  [project net ETH_RXD2]
PF9: U27.P1(PF9) ; port ETHERNET.ETH_RXD3  [project net ETH_RXD3]
PF10: U27.L4(PF10) ; port ETHERNET.ETH_RX_DV  [project net ETH_RX_DV]
PF11: U27.P3(PF11) ; port ETHERNET.ETH_TX_EN  [project net ETH_TX_EN]
PF12: U27.T1(PF12) ; port ETHERNET.ETH_TXD0  [project net ETH_TXD0]
PF13: U27.R2(PF13) ; port ETHERNET.ETH_TXD1  [project net ETH_TXD1]
PF14: U27.N2(PF14) ; port ETHERNET.ETH_RXD0  [project net ETH_RXD0]
PF15: U27.N1(PF15) ; port ETHERNET.ETH_RXD1  [project net ETH_RXD1]
PG0: U27.R13(PG0) ; port LCD.R0  [project net LCD_R0]
PG1: U27.R9(PG1) ; port LCD.G1  [project net LCD_G1]
PG2: U27.T11(PG2) ; port ARD_UNO_R3.D11, port STMOD+.SPI5_MOSI  [project net ARD_D11]
PG3: U27.R1(PG3) ; port ETHERNET.ETH_TXD2  [project net ETH_TXD2]
PG4: U27.P2(PG4) ; port ETHERNET.ETH_TXD3  [project net ETH_TXD3]
PG5: U27.M4(PG5) ; port STMOD+.CTS
PG6: U27.L3(PG6) ; port LCD.B3  [project net LCD_B3]
PG7: U27.L1(PG7) ; port AudioCodec.SAI1_MCLK_A, port TRACE.TRACECLK
PG8: U27.T14(PG8) ; port LCD.G7  [project net LCD_G7]
PG9: U27.T13(PG9) ; port STMOD+.IO4
PG10: U27.T10(PG10) ; port Peripherals.LED2  [project net LED2]
PG11: U27.U13(PG11) ; port LCD.R6  [project net LCD_R6]
PG12: U27.T9(PG12) ; port LCD.G0  [project net LCD_G0]
PG13: U27.U9(PG13) ; port LCD.LCD_DE  [project net LCD_DE]
PG14: U27.P6(PG14) ; port STMOD+.RTS
PG15: U27.R6(PG15) ; port LCD.B0  [project net LCD_B0]
PH0: R155.2 U27.A7(PH0-OSC_IN(PH0))
PH1: R154.2 U27.B7(PH1-OSC_OUT(PH1))
PH2: U27.E7(PH2) ; port ARD_UNO_R3.A5D  [project net ARD_A5D]
PH3: U27.B1(PH3) ; port LCD.B4  [project net LCD_B4]
PH4: U27.F4(PH4) ; port LCD.R4  [project net LCD_R4]
PH5: SB42.2 U27.F5(PH5)
PH6: U27.B2(PH6) ; port LCD.B5  [project net LCD_B5]
PH7: U27.D2(PH7) ; port STMOD+.MOSI
PH8: U27.C2(PH8) ; port ARD_UNO_R3.D12, port STMOD+.SPI5_MISO  [project net ARD_D12]
PH9: R153.2 U27.D8(PH9) ; port I2C1.SCL  [project net ARD_D15]
PN0: R72.2 U27.P17(PN0)
PN1: R66.2 U27.R17(PN1)
PN2: R52.2 U27.T17(PN2)
PN3: R42.2 U27.R15(PN3)
PN4: R70.2 U27.N17(PN4)
PN5: R67.2 U27.R16(PN5)
PN6: R71.2 U27.P15(PN6)
PN7: U27.T16(PN7) ; port USB1.USB1_OCP
PN8: R65.2 U27.P16(PN8)
PN9: R39.2 U27.T15(PN9)
PN10: R37.2 U27.U15(PN10)
PN11: R40.2 U27.U16(PN11)
PN12: U27.P14(PN12) ; port MicroSD.DECTECT
PO0: R61.2 U27.M17(PO0)
PO1: U27.K16(PO1) ; port Peripherals.LED1  [project net LED1]
PO2: R58.2 U27.K17(PO2)
PO3: R51.2 U27.M16(PO3)
PO4: R62.2 U27.N16(PO4)
PO5: U27.K15(PO5) ; port MicroSD.LDO_SEL
PP0: R56.2 U27.G17(PP0)
PP1: R55.2 U27.H16(PP1)
PP2: R47.2 U27.J17(PP2)
PP3: R45.2 U27.J16(PP3)
PP4: R57.2 U27.H15(PP4)
PP5: R44.2 U27.J14(PP5)
PP6: R54.2 U27.G16(PP6)
PP7: R53.2 U27.G15(PP7)
PP8: R59.2 U27.L16(PP8)
PP9: R64.2 U27.N14(PP9)
PP10: R63.2 U27.N15(PP10)
PP11: R50.2 U27.L15(PP11)
PP12: R49.2 U27.J15(PP12)
PP13: R60.2 U27.K14(PP13)
PP14: R48.2 U27.L17(PP14)
PP15: R46.2 U27.H17(PP15)
PQ0: U27.E5(PQ0) ; port Camera.TOF_INT
PQ1: U27.E4(PQ1) ; port Camera.IMU_INT1  [project net IMU_INT1]
PQ2: U27.E3(PQ2) ; port Camera.IMU_INT2  [project net IMU_INT2]
PQ3: U27.D3(PQ3) ; port LCD.LCD_ON/OFF  [project net LCD_ON/OFF]
PQ4: U27.D4(PQ4) ; port LCD.LCD_INT  [project net LCD_INT]
PQ5: U27.D5(PQ5) ; port Camera.TOF_LPn
PQ6: U27.A2(PQ6) ; port LCD.LCD_BL_CTRL  [project net LCD_BL_CTRL]
PQ7: U27.G5(PQ7) ; port MicroSD.PWR_SD_EN
PWR_ON: U27.E2(PWR_ON) ; port PWR_ON
UCPD1_CC1: U27.A6(UCPD1_CC1) ; port USB1.UCPD1_CC1
UCPD1_CC2: U27.B6(UCPD1_CC2) ; port USB1.UCPD1_CC2
NetC153_2: C153.2 R154.1 X2.3
NetC155_2: C155.2 R155.1 X2.1
NetC174_2: C174.2 R170.1 X3.1(X1)
NetC175_2: C175.2 R171.1 X3.2(X2)
NetR32_1: R32.1 U27.C6(OTG1_TXRTUNE)
NetR33_1: R33.1 U27.P5(CSI_REXT)
NetR34_1: R34.1 U27.D6(OTG2_TXRTUNE)
NetTP8_1: TP8.1 U27.C3(OTG1_ID)
NetTP9_1: TP9.1 U27.E6(OTG2_ID)
NetTP23_1: TP23.1 U27.C4(NC)
NetTP24_1: TP24.1 U27.B4(NC)

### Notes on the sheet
- I2C PULL UP
- I2C1
- I2C2
- PH9
- PC1
- PD14
- PD4

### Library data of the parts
C153 C155 = MCD-01932: Capacitor, MLCC, 8.2pF, 50V, NPO, +/-0.25pF, 0402, T=0.5mm; Part_Preference: Recommended; Manufacturer: YAGEO; Manufacturer_Part_Number: CC0402CRNPO9BN8R2; Component_Country_Of_Origin: China; ShowFields: YES; ID: 4032
C174 C175 = MCD-01775: Capacitor, MLCC, 3.3pF, 50V, NPO, +/-0.1pF, 0402, T=0.5mm; Part_Preference: Recommended; Manufacturer: YAGEO; Manufacturer_Part_Number: CC0402BRNPO9BN3R3; Component_Country_Of_Origin: China; ShowFields: YES; ID: 3875
HW5 = MCD-03192: Socket_IC, BGA289, 19.225x19.225x8.25, pitch 0.8mm; Part_Preference: Recommended; Manufacturer: IRONWOOD; ShowFields: YES; ID: 5308; Component_Country_Of_Origin: USA
R32-R34 = MCD-00417: Resistor, 200R, 0402, +/-1%, 1/16W; Part_Preference: Recommended; Manufacturer: YAGEO; Manufacturer_Part_Number: RC0402FR-07200RL; Component_Country_Of_Origin: China; ShowFields: YES; ID: 2860
R36 R38 R149 R153 = MCD-00068: Resistor, 1K5, 0402, +/-1%, 1/16W; Manufacturer_Part_Number: RC0402FR-071K5L; Manufacturer: YAGEO; Part_Preference: Recommended; Order_Code_RS: 9239251; Component_Country_Of_Origin: China; ShowFields: YES; ID: 2524
R37 R39 R40 R42 R44-R67 R70-R72 R170 R171 = MCD-00052: Resistor, 0R, 0402, +/-5%, 1/16W; Part_Preference: Recommended; Manufacturer: YAGEO; Manufacturer_Part_Number: RC0402JR-070RL; Order_Code_RS: 9232516RL; Component_Country_Of_Origin: China; ShowFields: YES; ID: 2540
R154 R155 = MCD-00052: as R12 on sheet Power
SB6 SB8 = MCD-01618: Resistor, 0R, SB0402, 5%, 0.063W; Part_Preference: Recommended; Manufacturer: YAGEO; Manufacturer_Part_Number: RC0402JR-070RL; ShowFields: YES; ID: 3718; Order_Code_RS: 618-5804; Component_Country_Of_Origin: China
SB7 SB42-SB44 = MCD-01618: Resistor, 0R, SB0402, 5%, 0.063W; Manufacturer_Part_Number: RC0402JR-070RL; Manufacturer: YAGEO; Part_Preference: Recommended; ShowFields: YES; ID: 3718; Order_Code_RS: 618-5804; Component_Country_Of_Origin: China
SB41 = MCD-00071: Resistor, 0R, SB0603, 5%, 0.1W; Manufacturer_Part_Number: RC0603JR-070RL; Manufacturer: YAGEO; Part_Preference: Recommended; Manufacturer_HQ_COO: Unknown; ShowFields: YES; ID: 2521; Order_Code_RS: 199-5647; Component_Country_Of_Origin: China
TP8 TP9 TP23 TP24 = MCD-00074: Test Point, SMD, 1mm; Part_Type: Misc; Part_Preference: Recommended; ShowFields: YES; ID: 2518; Component_Country_Of_Origin: Unknown
TP21 TP22 = MCD-00177: as TP4 on sheet Power
U27 = MCD-03176: Neural MCU, Arm® Cortex®-M55, 600-Gops ST Neural-ART Accelerator, Neo-Chrom 2.5D GPU, 4.2 MB contiguous SRAM; Part_Type: IC; Part_Preference: Recommended; Manufacturer: STMICROELECTRONICS; ShowFields: YES; ID: 5292; Component_Country_Of_Origin: Unknown
X2 = MCD-02262: Crystal, 48MHz, 7pF, +/-20 ppm, 80R, 1.6x1.2mm; Part_Type: Crystal_Osc; Manufacturer_Part_Number: NX1612SA-48MHZ-EXS00A-CS13734; Manufacturer: NDK; Part_Preference: Recommended; Component_Country_Of_Origin: Unknown; ShowFields: YES; ID: 4362
X3 = MCD-01479: Crystal, 32.768kHz, 6pF, +/-20ppm, 80K, 2.05x1.2mm; BMS_Part_Number: 9157049; Part_Type: Crystal_Osc; Part_Preference: Recommended; Manufacturer: NDK; Manufacturer_Part_Number: NX2012SA-32.768KHZ-EXS00A-MU00527; Component_Country_Of_Origin: Unknown; ShowFields: YES; ID: 3579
